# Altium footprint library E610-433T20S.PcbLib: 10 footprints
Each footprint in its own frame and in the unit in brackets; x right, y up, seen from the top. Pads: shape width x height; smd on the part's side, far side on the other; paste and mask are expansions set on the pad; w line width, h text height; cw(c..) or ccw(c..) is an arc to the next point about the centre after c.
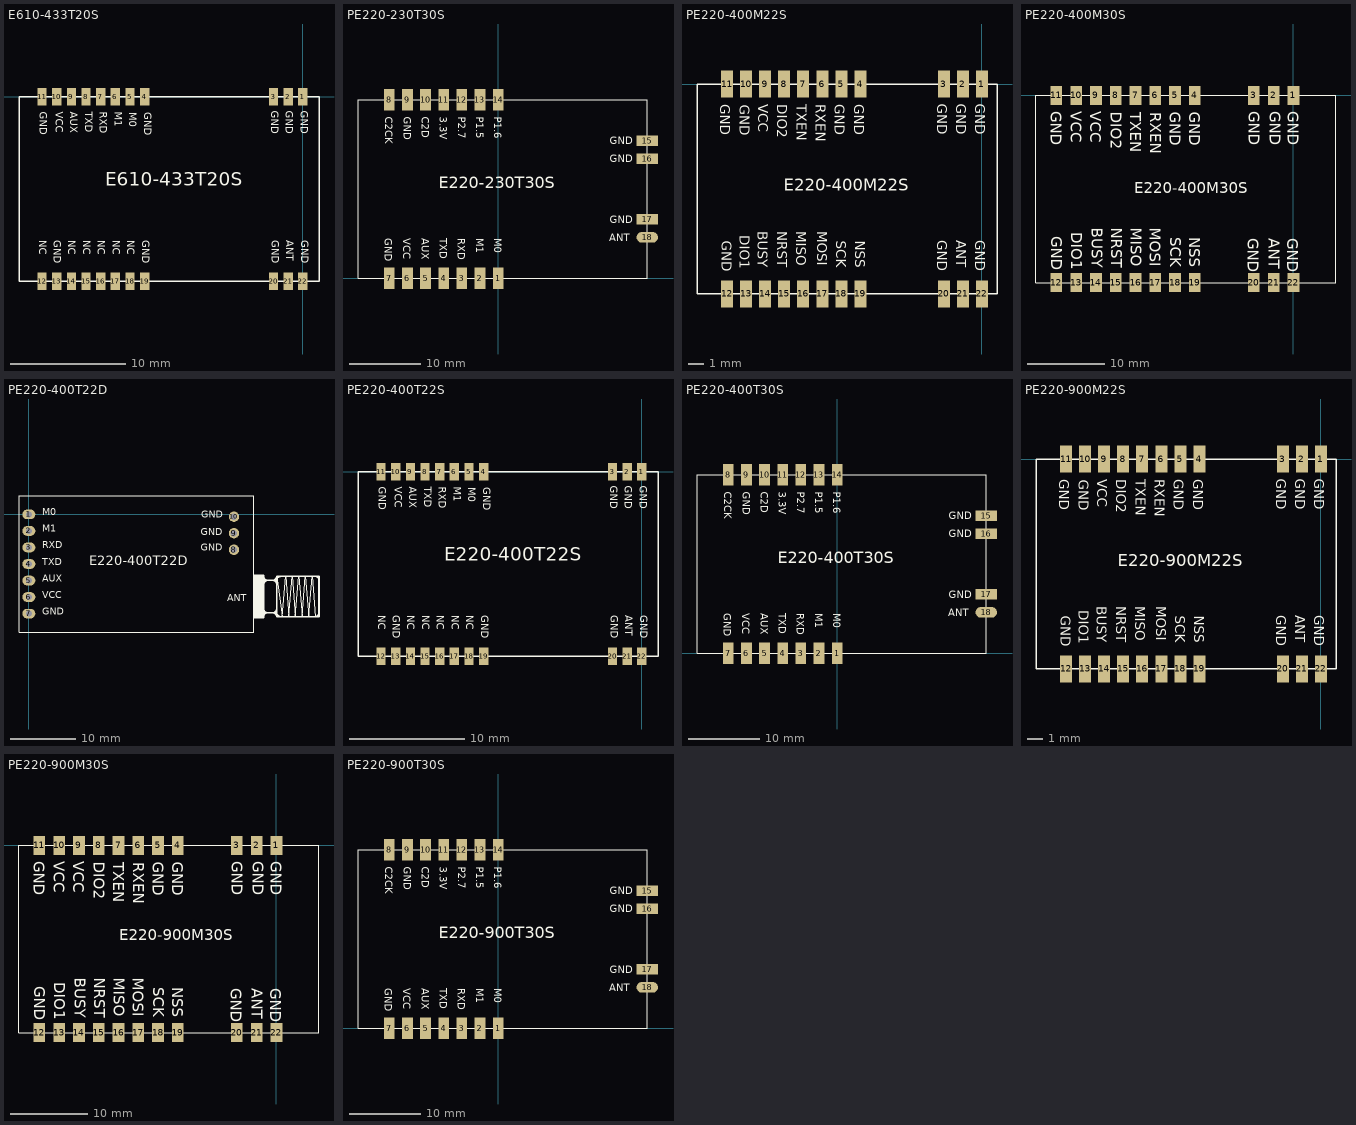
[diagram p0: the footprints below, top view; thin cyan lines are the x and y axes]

## E610-433T20S [mm] "26mm**16mm*3.23mm-S"
pads (22):
  rect 0.8x1.5 smd: 1(0,0) 2(-1.27,0) 3(-2.54,0) 4(-13.71,0) 5(-14.98,0) 6(-16.25,0) 7(-17.52,0) 8(-18.79,0) 9(-20.06,0) 10(-21.33,0) 11(-22.6,0) 12(-22.6,-16) 13(-21.33,-16) 14(-20.06,-16) 15(-18.79,-16) 16(-17.52,-16) 17(-16.25,-16) 18(-14.98,-16) 19(-13.71,-16) 20(-2.54,-16) 21(-1.27,-16) 22(0,-16)
Top Overlay:
  lines w0.127: -24.6,-16 -24.6,0 1.4,0 1.4,-16 -24.6,-16
  text "GND" at -0.408,-1.224 h1.1
  text "E610-433T20S" at -17.107,-8.126 h2
  text "M0" at -15.257,-1.351 h1.1
  text "M1" at -16.536,-1.301 h1.1
  text "RXD" at -17.814,-1.301 h1.1
  text "TXD" at -19.093,-1.301 h1.1
  text "AUX" at -20.372,-1.301 h1.1
  text "VCC" at -21.651,-1.301 h1.1
  text "GND" at -23.01,-1.301 h1.1
  text "GND" at -13.97,-1.351 h1.1
  text "GND" at -0.358,-12.441 h1.1
  text "ANT" at -1.637,-12.441 h1.1
  text "GND" at -2.916,-12.441 h1.1
  text "GND" at -2.966,-1.224 h1.1
  text "GND" at -1.687,-1.224 h1.1
  text "NC" at -23.06,-12.441 h1.1
  text "GND" at -21.811,-12.441 h1.1
  text "NC" at -20.532,-12.441 h1.1
  text "NC" at -19.253,-12.441 h1.1
  text "NC" at -17.974,-12.441 h1.1
  text "NC" at -16.696,-12.441 h1.1
  text "NC" at -15.417,-12.441 h1.1
  text "GND" at -14.138,-12.441 h1.1

## PE220-230T30S [mm] "40.5mm*25mm*3.80mm-S"
pads (18):
  rect 1.5x3 smd: 1(0,0) 2(-2.54,0) 3(-5.08,0) 4(-7.62,0) 5(-10.16,0) 6(-12.7,0) 7(-15.24,0) 8(-15.24,25) 9(-12.7,25) 10(-10.16,25) 11(-7.62,25) 12(-5.08,25) 13(-2.54,25) 14(0,25)
  rect 3x1.5 smd: 15(20.88,19.27) 16(20.88,16.73) 17(20.88,8.27)
  oval 3x1.5 smd: 18(20.88,5.73)
Top Overlay:
  lines w0.127: -19.62,0 20.88,0 20.88,25 -19.62,25 -19.62,0
  text "C2D" at -10.73,22.606 h1
  text "GND" at 15.602,18.73 h1
  text "GND" at 15.602,16.22 h1
  text "P1.6" at -0.557,22.592 h1
  text "P1.5" at -3.067,22.592 h1
  text "P2.7" at -5.617,22.592 h1
  text "3.3V" at -8.147,22.592 h1
  text "GND" at -13.237,22.592 h1
  text "C2CK" at -15.827,22.592 h1
  text "GND" at -15.847,5.575 h1
  text "VCC" at -13.257,5.575 h1
  text "AUX" at -10.707,5.575 h1
  text "TXD" at -8.167,5.575 h1
  text "RXD" at -5.637,5.575 h1
  text "M1" at -3.087,5.575 h1
  text "M0" at -0.577,5.575 h1
  text "ANT" at 15.554,5.17 h1
  text "GND" at 15.602,7.72 h1
  text "E220-230T30S" at -8.317,12.065 h2.8

## PE220-400M22S [mm] "20mm*14mm*2.8mm-S"
pads (22):
  rect 0.8x1.8 smd: 1(0,0) 2(-1.27,0) 3(-2.54,0) 4(-8.11,0) 5(-9.38,0) 6(-10.65,0) 7(-11.92,0) 8(-13.19,0) 9(-14.46,0) 10(-15.73,0) 11(-17,0) 12(-17,-14) 13(-15.73,-14) 14(-14.46,-14) 15(-13.19,-14) 16(-11.92,-14) 17(-10.65,-14) 18(-9.38,-14) 19(-8.11,-14) 20(-2.54,-14) 21(-1.27,-14) 22(0,-14)
Top Overlay:
  lines w0.1: -19,-14 1,-14 1,0 -19,0 -19,-14
  text "E220-400M22S" at -13.208,-7.112 h0.8
  text "NSS" at -8.459,-10.444 h0.65
  text "SCK" at -9.729,-10.444 h0.65
  text "MOSI" at -10.999,-9.809 h0.65
  text "MISO" at -12.396,-9.809 h0.65
  text "NRST" at -13.666,-9.809 h0.65
  text "BUSY" at -14.936,-9.809 h0.65
  text "DIO1" at -16.14,-10.097 h0.65
  text "GND" at -17.349,-10.444 h0.65
  text "GND" at -2.996,-10.428 h0.65
  text "ANT" at -1.717,-10.428 h0.65
  text "GND" at -0.438,-10.428 h0.65
  text "GND" at -0.438,-1.323 h0.65
  text "GND" at -1.717,-1.323 h0.65
  text "GND" at -2.996,-1.323 h0.65
  text "GND" at -17.45,-1.353 h0.65
  text "GND" at -16.14,-1.373 h0.65
  text "VCC" at -14.922,-1.353 h0.65
  text "DIO2" at -13.643,-1.353 h0.65
  text "TXEN" at -12.364,-1.353 h0.65
  text "RXEN" at -11.086,-1.353 h0.65
  text "GND" at -9.807,-1.353 h0.65
  text "GND" at -8.528,-1.353 h0.65

## PE220-400M30S [mm] "38.5mm*24mm*3.8mm-S"
pads (22):
  rect 1.5x2.5 smd: 1(0,0) 2(-2.54,0) 3(-5.08,0) 4(-12.65,0) 5(-15.19,0) 6(-17.73,0) 7(-20.27,0) 8(-22.81,0) 9(-25.35,0) 10(-27.89,0) 11(-30.43,0) 12(-30.43,-24) 13(-27.89,-24) 14(-25.35,-24) 15(-22.81,-24) 16(-20.27,-24) 17(-17.73,-24) 18(-15.19,-24) 19(-12.65,-24) 20(-5.08,-24) 21(-2.54,-24) 22(0,-24)
Top Overlay:
  lines w0.1: -33.04,-24 5.46,-24 5.46,0 -33.04,0 -33.04,-24
  text "E220-400M30S" at -20.447,-12.573 h1.4
  text "GND" at -13.366,-2.096 h1.4
  text "GND" at -15.899,-2.096 h1.4
  text "RXEN" at -18.402,-2.169 h1.4
  text "TXEN" at -20.935,-2.169 h1.4
  text "DIO2" at -23.438,-2.117 h1.4
  text "VCC" at -26.076,-2.051 h1.4
  text "VCC" at -28.61,-2.051 h1.4
  text "GND" at -31.143,-2.051 h1.4
  text "GND" at -5.743,-1.991 h1.4
  text "GND" at -3.07,-1.991 h1.4
  text "GND" at -0.748,-1.991 h1.4
  text "GND" at -0.775,-18.291 h1.4
  text "ANT" at -3.202,-18.291 h1.4
  text "GND" at -5.844,-18.291 h1.4
  text "GND" at -31.079,-18.064 h1.4
  text "DIO1" at -28.532,-17.552 h1.4
  text "BUSY" at -25.871,-16.979 h1.4
  text "NRST" at -23.406,-16.979 h1.4
  text "MISO" at -20.881,-16.979 h1.4
  text "MOSI" at -18.416,-16.979 h1.4
  text "SCK" at -15.816,-18.17 h1.4
  text "NSS" at -13.351,-18.17 h1.4

## PE220-400T22D [mm] "36mm*21mm-D/SMA长度12.5mm"
pads (10):
  oval 2x1.5 hole 0.9: 1(0,0) 2(0,-2.54) 3(0,-5.08) 4(0,-7.62) 5(0,-10.16) 6(0,-12.7) 7(0,-15.24)
  round 1.6 hole 1: 8(31.49,-5.43) 9(31.49,-2.89) 10(31.49,-0.35)
Top Overlay:
  rectangle: 34.54,-15.87 36.04,-9.37
  rectangle: 34.54,-15.865 36.04,-9.365
  lines w0.1: 38.89,-15.72 39.41,-9.52 ; 38.89,-15.72 38.04,-9.52 38.89,-15.72 ; 38.89,-15.72 39.41,-9.52 ; 39.41,-9.52 39.92,-15.72 ; 39.41,-9.52 39.92,-15.72 ; 39.92,-15.72 40.43,-9.52 ; 39.92,-15.72 40.43,-9.52 ; 40.43,-9.52 40.91,-15.72 ; 40.43,-9.52 40.91,-15.72 ; 40.91,-15.72 41.43,-9.52 ; 40.91,-15.72 41.43,-9.52 ; 41.43,-9.52 41.94,-15.72 ; 41.43,-9.52 41.94,-15.72 ; 41.94,-15.72 42.43,-9.52 ; 41.94,-15.72 42.43,-9.52 ; 42.43,-9.52 42.95,-15.72 ; 42.43,-9.52 42.95,-15.72 ; 42.95,-15.72 43.47,-9.52 ; 42.95,-15.72 43.47,-9.52 ; 43.47,-9.52 43.98,-15.72 43.47,-9.52 ; -1.51,-18.12 34.558,-18.12 34.558,2.88 -1.51,2.88 -1.51,-18.12
  lines w0.254: 34.54,-15.87 36.04,-15.87 ; 34.54,-15.87 34.54,-9.37 ; 34.54,-15.87 36.04,-15.87 ; 34.54,-15.87 34.54,-9.37 ; 34.54,-9.37 36.04,-9.37 ; 34.54,-9.37 36.04,-9.37 ; 36.04,-15.87 36.04,-9.37 ; 36.04,-15.87 36.04,-9.37 ; 36.04,-14.47 ccw(c36.69,-14.47) 36.69,-15.12 ; 36.04,-14.47 ccw(c36.69,-14.47) 36.69,-15.12 ; 36.04,-14.47 36.04,-14.1 36.04,-14.47 ; 36.04,-10.82 cw(c36.74,-10.82) 36.74,-10.12 ; 36.04,-10.82 cw(c36.74,-10.82) 36.74,-10.12 ; 36.04,-10.82 36.04,-11.74 36.04,-10.82 ; 36.04,-9.49 ccw(c36.67,-9.49) 36.67,-10.12 ; 36.04,-9.49 ccw(c36.67,-9.49) 36.67,-10.12 ; 36.04,-9.49 36.04,-9.37 ; 36.04,-9.49 36.04,-9.37 ; 36.59,-15.12 ccw(c36.59,-15.67) 36.04,-15.67 cw(c36.59,-15.67) 36.59,-15.12 ; 36.59,-15.12 37.44,-15.12 ; 36.59,-15.12 37.44,-15.12 ; 36.67,-10.12 37.44,-10.12 ; 36.67,-10.12 37.44,-10.12 ; 36.69,-15.12 37.41,-15.12 ; 36.69,-15.12 37.41,-15.12 ; 36.74,-10.12 37.44,-10.12 ; 36.74,-10.12 37.44,-10.12 ; 37.41,-15.12 ccw(c37.41,-14.49) 38.04,-14.49 cw(c37.41,-14.49) 37.41,-15.12 ; 37.44,-15.12 cw(c37.44,-15.72) 38.04,-15.72 ; 37.44,-15.12 cw(c37.44,-15.72) 38.04,-15.72 ; 37.44,-10.12 cw(c37.44,-10.72) 38.04,-10.72 ccw(c37.44,-10.72) 37.44,-10.12 ; 37.44,-10.12 ccw(c37.44,-9.52) 38.04,-9.52 ; 37.44,-10.12 ccw(c37.44,-9.52) 38.04,-9.52 ; 38.04,-15.72 38.04,-9.52 ; 38.04,-15.72 44.54,-15.72 ; 38.04,-15.72 38.04,-9.52 ; 38.04,-15.72 44.54,-15.72 ; 38.04,-9.52 44.54,-9.52 ; 38.04,-9.52 44.54,-9.52 ; 38.72,-15.72 cw(c38.72,-15.04) 38.04,-15.04 ccw(c38.72,-15.04) 38.72,-15.72 ; 38.72,-15.72 38.87,-15.72 38.72,-15.72 ; 43.92,-15.72 ccw(c43.92,-15.1) 44.54,-15.1 cw(c43.92,-15.1) 43.92,-15.72 ; 43.92,-15.72 43.69,-15.72 43.92,-15.72 ; 44,-9.52 cw(c44,-10.06) 44.54,-10.06 ccw(c44,-10.06) 44,-9.52 ; 44,-9.52 43.6,-9.52 44,-9.52 ; 44.54,-15.72 44.54,-9.52 ; 44.54,-15.72 44.54,-9.52 ; 35.87,-15.12 38.04,-15.12 35.87,-15.12 ; 36.04,-10.12 38.04,-10.12 36.04,-10.12 ; 38.04,-10.13 cw(c38.65,-10.13) 38.65,-9.52 ccw(c38.65,-10.13) 38.04,-10.13
  text "GND" at 2.063,-15.78 h1.8
  text "VCC" at 2.063,-13.24 h1.8
  text "AUX" at 2.063,-10.7 h1.8
  text "TXD" at 2.063,-8.16 h1.8
  text "RXD" at 2.063,-5.62 h1.8
  text "M1" at 2.063,-3.08 h1.8
  text "M0" at 2.063,-0.54 h1.8
  text "ANT" at 30.48,-13.716 h1.8
  text "GND" at 26.447,-0.921 h1.8
  text "GND" at 26.416,-3.556 h1.8
  text "GND" at 26.416,-5.969 h1.8
  text "E220-400T22D" at 9.271,-8.382 h2.5

## PE220-400T22S [mm] "26mm**16mm*3.23mm-S"
pads (22):
  rect 0.8x1.5 smd: 1(0,0) 2(-1.27,0) 3(-2.54,0) 4(-13.71,0) 5(-14.98,0) 6(-16.25,0) 7(-17.52,0) 8(-18.79,0) 9(-20.06,0) 10(-21.33,0) 11(-22.6,0) 12(-22.6,-16) 13(-21.33,-16) 14(-20.06,-16) 15(-18.79,-16) 16(-17.52,-16) 17(-16.25,-16) 18(-14.98,-16) 19(-13.71,-16) 20(-2.54,-16) 21(-1.27,-16) 22(0,-16)
Top Overlay:
  lines w0.127: -24.6,-16 -24.6,0 1.4,0 1.4,-16 -24.6,-16
  text "GND" at -0.408,-1.224 h1.1
  text "E220-400T22S" at -17.107,-8.126 h2
  text "M0" at -15.257,-1.351 h1.1
  text "M1" at -16.536,-1.301 h1.1
  text "RXD" at -17.814,-1.301 h1.1
  text "TXD" at -19.093,-1.301 h1.1
  text "AUX" at -20.372,-1.301 h1.1
  text "VCC" at -21.651,-1.301 h1.1
  text "GND" at -23.01,-1.301 h1.1
  text "GND" at -13.97,-1.351 h1.1
  text "NC" at -23.06,-12.441 h1.1
  text "GND" at -21.811,-12.441 h1.1
  text "NC" at -20.532,-12.441 h1.1
  text "NC" at -19.253,-12.441 h1.1
  text "NC" at -17.974,-12.441 h1.1
  text "NC" at -16.696,-12.441 h1.1
  text "NC" at -15.417,-12.441 h1.1
  text "GND" at -14.138,-12.441 h1.1
  text "GND" at -0.358,-12.441 h1.1
  text "ANT" at -1.637,-12.441 h1.1
  text "GND" at -2.916,-12.441 h1.1
  text "GND" at -2.966,-1.224 h1.1
  text "GND" at -1.687,-1.224 h1.1

## PE220-400T30S [mm] "40.5mm*25mm*3.80mm-S"
pads (18):
  rect 1.5x3 smd: 1(0,0) 2(-2.54,0) 3(-5.08,0) 4(-7.62,0) 5(-10.16,0) 6(-12.7,0) 7(-15.24,0) 8(-15.24,25) 9(-12.7,25) 10(-10.16,25) 11(-7.62,25) 12(-5.08,25) 13(-2.54,25) 14(0,25)
  rect 3x1.5 smd: 15(20.88,19.27) 16(20.88,16.73) 17(20.88,8.27)
  oval 3x1.5 smd: 18(20.88,5.73)
Top Overlay:
  lines w0.127: -19.62,0 20.88,0 20.88,25 -19.62,25 -19.62,0
  text "C2D" at -10.73,22.606 h1
  text "GND" at 15.602,18.73 h1
  text "GND" at 15.602,16.22 h1
  text "P1.6" at -0.557,22.592 h1
  text "P1.5" at -3.067,22.592 h1
  text "P2.7" at -5.617,22.592 h1
  text "3.3V" at -8.147,22.592 h1
  text "GND" at -13.237,22.592 h1
  text "C2CK" at -15.827,22.592 h1
  text "GND" at -15.847,5.575 h1
  text "VCC" at -13.257,5.575 h1
  text "AUX" at -10.707,5.575 h1
  text "TXD" at -8.167,5.575 h1
  text "RXD" at -5.637,5.575 h1
  text "M1" at -3.087,5.575 h1
  text "M0" at -0.577,5.575 h1
  text "ANT" at 15.554,5.17 h1
  text "GND" at 15.602,7.72 h1
  text "E220-400T30S" at -8.317,12.065 h2.8

## PE220-900M22S [mm] "20mm*14mm*2.8mm-S"
pads (22):
  rect 0.8x1.8 smd: 1(0,0) 2(-1.27,0) 3(-2.54,0) 4(-8.11,0) 5(-9.38,0) 6(-10.65,0) 7(-11.92,0) 8(-13.19,0) 9(-14.46,0) 10(-15.73,0) 11(-17,0) 12(-17,-14) 13(-15.73,-14) 14(-14.46,-14) 15(-13.19,-14) 16(-11.92,-14) 17(-10.65,-14) 18(-9.38,-14) 19(-8.11,-14) 20(-2.54,-14) 21(-1.27,-14) 22(0,-14)
Top Overlay:
  lines w0.1: -19,-14 1,-14 1,0 -19,0 -19,-14
  text "E220-900M22S" at -13.539,-7.142 h0.8
  text "NSS" at -8.459,-10.444 h0.65
  text "SCK" at -9.729,-10.444 h0.65
  text "MOSI" at -10.999,-9.809 h0.65
  text "MISO" at -12.396,-9.809 h0.65
  text "NRST" at -13.666,-9.809 h0.65
  text "BUSY" at -14.936,-9.809 h0.65
  text "DIO1" at -16.14,-10.097 h0.65
  text "GND" at -17.349,-10.444 h0.65
  text "GND" at -2.996,-10.428 h0.65
  text "ANT" at -1.717,-10.428 h0.65
  text "GND" at -0.438,-10.428 h0.65
  text "GND" at -0.438,-1.323 h0.65
  text "GND" at -1.717,-1.323 h0.65
  text "GND" at -2.996,-1.323 h0.65
  text "GND" at -17.45,-1.353 h0.65
  text "GND" at -16.14,-1.373 h0.65
  text "VCC" at -14.922,-1.353 h0.65
  text "DIO2" at -13.643,-1.353 h0.65
  text "TXEN" at -12.364,-1.353 h0.65
  text "RXEN" at -11.086,-1.353 h0.65
  text "GND" at -9.807,-1.353 h0.65
  text "GND" at -8.528,-1.353 h0.65

## PE220-900M30S [mm] "38.5mm*24mm*3.8mm-S"
pads (22):
  rect 1.5x2.5 smd: 1(0,0) 2(-2.54,0) 3(-5.08,0) 4(-12.65,0) 5(-15.19,0) 6(-17.73,0) 7(-20.27,0) 8(-22.81,0) 9(-25.35,0) 10(-27.89,0) 11(-30.43,0) 12(-30.43,-24) 13(-27.89,-24) 14(-25.35,-24) 15(-22.81,-24) 16(-20.27,-24) 17(-17.73,-24) 18(-15.19,-24) 19(-12.65,-24) 20(-5.08,-24) 21(-2.54,-24) 22(0,-24)
Top Overlay:
  lines w0.1: -33.04,-24 -33.04,0 5.46,0 5.46,-24 -33.04,-24
  text "NSS" at -13.351,-18.17 h1.4
  text "SCK" at -15.816,-18.17 h1.4
  text "MOSI" at -18.416,-16.979 h1.4
  text "MISO" at -20.881,-16.979 h1.4
  text "NRST" at -23.406,-16.979 h1.4
  text "BUSY" at -25.871,-16.979 h1.4
  text "DIO1" at -28.532,-17.552 h1.4
  text "GND" at -31.079,-18.064 h1.4
  text "GND" at -5.844,-18.291 h1.4
  text "ANT" at -3.202,-18.291 h1.4
  text "GND" at -0.775,-18.291 h1.4
  text "GND" at -0.748,-1.991 h1.4
  text "GND" at -3.07,-1.991 h1.4
  text "GND" at -5.743,-1.991 h1.4
  text "GND" at -31.143,-2.051 h1.4
  text "VCC" at -28.61,-2.051 h1.4
  text "VCC" at -26.076,-2.051 h1.4
  text "DIO2" at -23.438,-2.117 h1.4
  text "TXEN" at -20.935,-2.169 h1.4
  text "RXEN" at -18.402,-2.169 h1.4
  text "GND" at -15.899,-2.096 h1.4
  text "GND" at -13.366,-2.096 h1.4
  text "E220-900M30S" at -20.193,-12.192 h1.4

## PE220-900T30S [mm] "40.5mm*25mm*3.80mm-S"
pads (18):
  rect 1.5x3 smd: 1(0,0) 2(-2.54,0) 3(-5.08,0) 4(-7.62,0) 5(-10.16,0) 6(-12.7,0) 7(-15.24,0) 8(-15.24,25) 9(-12.7,25) 10(-10.16,25) 11(-7.62,25) 12(-5.08,25) 13(-2.54,25) 14(0,25)
  rect 3x1.5 smd: 15(20.88,19.27) 16(20.88,16.73) 17(20.88,8.27)
  oval 3x1.5 smd: 18(20.88,5.73)
Top Overlay:
  lines w0.127: -19.62,0 -19.62,25 20.88,25 20.88,0 -19.62,0
  text "E220-900T30S" at -8.317,12.065 h2.8
  text "GND" at 15.602,7.72 h1
  text "ANT" at 15.554,5.17 h1
  text "M0" at -0.577,5.575 h1
  text "M1" at -3.087,5.575 h1
  text "RXD" at -5.637,5.575 h1
  text "TXD" at -8.167,5.575 h1
  text "AUX" at -10.707,5.575 h1
  text "VCC" at -13.257,5.575 h1
  text "GND" at -15.847,5.575 h1
  text "C2CK" at -15.827,22.592 h1
  text "GND" at -13.237,22.592 h1
  text "3.3V" at -8.147,22.592 h1
  text "P2.7" at -5.617,22.592 h1
  text "P1.5" at -3.067,22.592 h1
  text "P1.6" at -0.557,22.592 h1
  text "GND" at 15.602,16.22 h1
  text "GND" at 15.602,18.73 h1
  text "C2D" at -10.73,22.606 h1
